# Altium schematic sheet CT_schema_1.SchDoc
size 461 x 273 mm
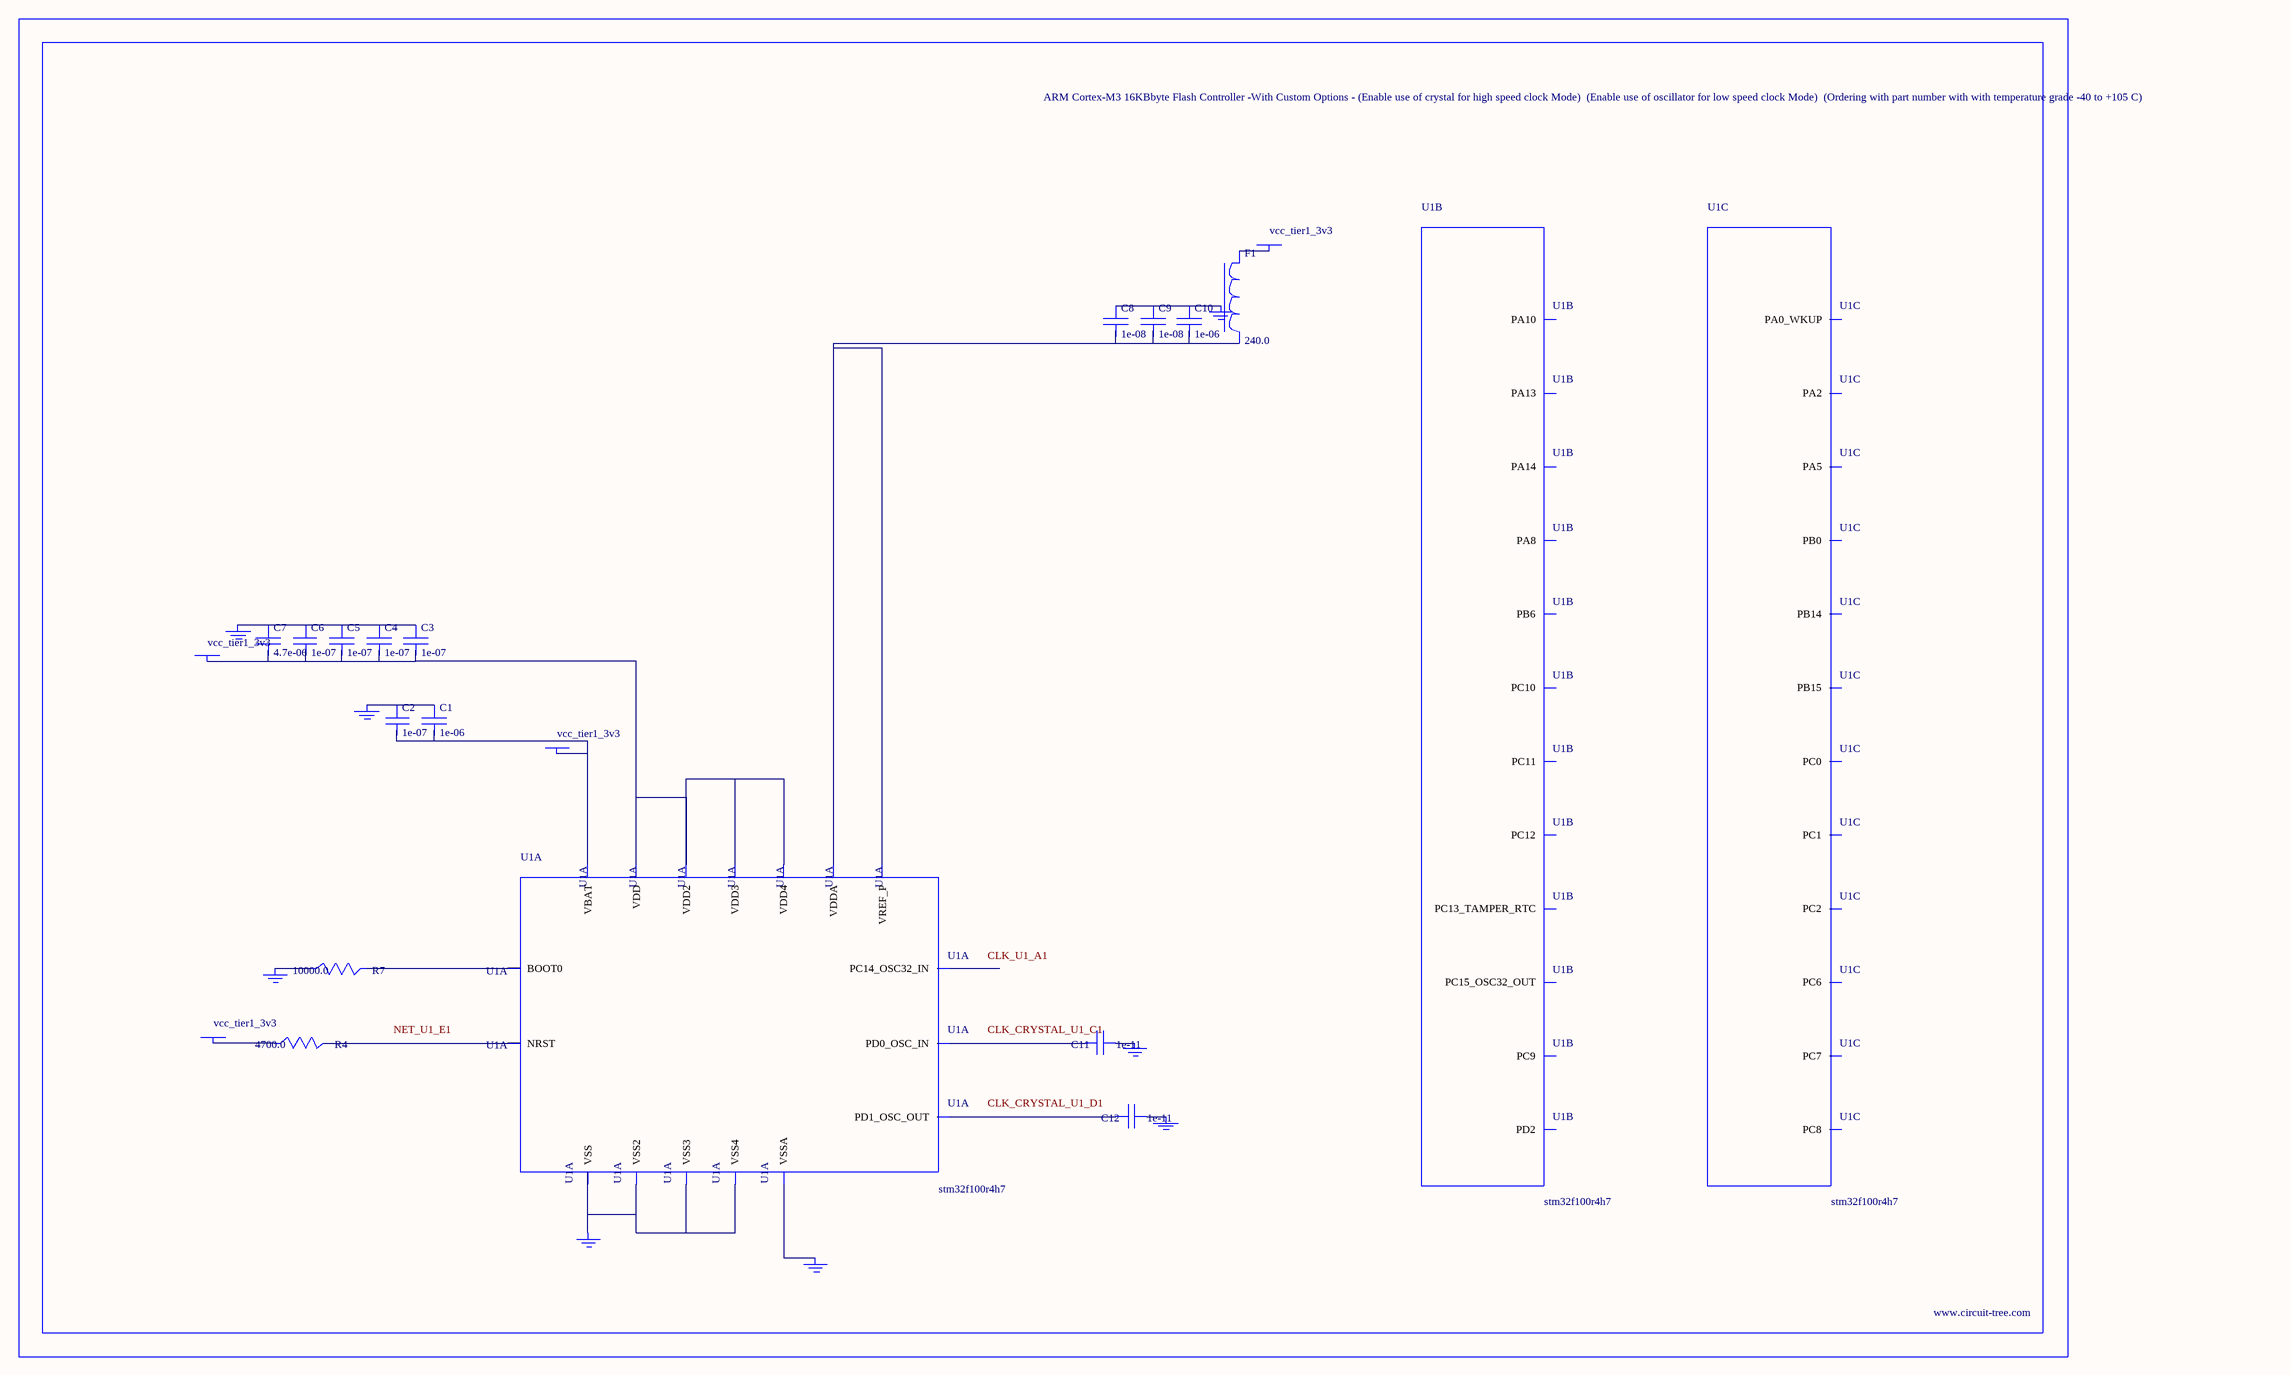
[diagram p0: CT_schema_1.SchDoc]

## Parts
BORDER0  (no value)
C1  1e-06  [C0603]
C2  1e-07  [C0603]
C3  1e-07  [C0603]
C4  1e-07  [C0603]
C5  1e-07  [C0603]
C6  1e-07  [C0603]
C7  4.7e-06  [C0603]
C8  1e-08  [C0603]
C9  1e-08  [C0603]
C10  1e-06  [C0603]
C11  1e-11  [C0402]
C12  1e-11  [C0402]
F1  240.0  [L0603]
GND_INSTANCE_0_0  (no value)
GND_INSTANCE_0_1  (no value)
GND_INSTANCE_0_2  (no value)
GND_INSTANCE_0_3  (no value)
GND_INSTANCE_0_4  (no value)
GND_INSTANCE_0_5  (no value)
GND_INSTANCE_0_6  (no value)
GND_INSTANCE_0_7  (no value)
POWER_INSTANCE_0_0  vcc_tier1_3v3
POWER_INSTANCE_0_1  vcc_tier1_3v3
POWER_INSTANCE_0_2  vcc_tier1_3v3
POWER_INSTANCE_0_3  vcc_tier1_3v3
R4  4700.0  [R0603]
R7  10000.0  [R0603]
U1  stm32f100r4h7  [TFBGA64]  (parts A,B,C of 5)

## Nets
NetC1_1: C1.1 C2.1 GND_INSTANCE_0_0.0(GND)
NetC1_2: C1.2 C2.2 POWER_INSTANCE_0_0.0(PWR) U1.B2(VBAT)
NetC3_1: C3.1 C4.1 C5.1 C6.1 C7.1 GND_INSTANCE_0_2.0(GND)
NetC3_2: C3.2 C4.2 C5.2 C6.2 C7.2 POWER_INSTANCE_0_2.0(PWR) U1.D2(VDD) U1.E4(VDD2) U1.E5(VDD3) U1.E6(VDD4)
NetC8_1: C8.1 C9.1 C10.1 GND_INSTANCE_0_1.0(GND)
NetC8_2: C8.2 C9.2 C10.2 F1.2 U1.G1(VREF_P) U1.H1(VDDA)
NetC11_1: C11.1 GND_INSTANCE_0_4.0(GND)
NetC11_2: C11.2 U1.C1(PD0_OSC_IN)
NetC12_1: C12.1 GND_INSTANCE_0_5.0(GND)
NetC12_2: C12.2 U1.D1(PD1_OSC_OUT)
NetF1_1: F1.1 POWER_INSTANCE_0_1.0(PWR)
NetGND_INSTANCE_0_3_0: GND_INSTANCE_0_3.0(GND) R7.1
NetGND_INSTANCE_0_6_0: GND_INSTANCE_0_6.0(GND) U1.F1(VSSA)
NetGND_INSTANCE_0_7_0: GND_INSTANCE_0_7.0(GND) U1.C2(VSS) U1.D4(VSS2) U1.D5(VSS3) U1.D6(VSS4)
NetPOWER_INSTANCE_0_3_0: POWER_INSTANCE_0_3.0(PWR) R4.1
NetR4_2: R4.2 U1.E1(NRST)
NetR7_2: R7.2 U1.B4(BOOT0)

Not connected (* = marked no-connect by the designer): U1 A1(PC14_OSC32_IN) A2(PC13_TAMPER_RTC) A7(PA14) A8(PA13) B1(PC15_OSC32_OUT) B5(PD2) B6(PC11) B7(PC10) C5(PC12) C6(PA10) D3(PB6) D7(PA8) D8(PC9) E2(PC1) E3(PC0) E7(PC7) E8(PC8) F2(PC2) F3(PA2) F4(PA5) F5(PB0) F6(PC6) F7(PB15) F8(PB14) G2(PA0_WKUP)

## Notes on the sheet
- Labels drawn without touching a wire or pin: CLK_CRYSTAL_U1_C1, CLK_CRYSTAL_U1_D1, CLK_U1_A1, NET_U1_E1

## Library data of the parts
BORDER0 = BORDER_PAGE0
C1 C10 = C0603C105K3RACTU
C2-C6 = 06035C104K4Z2A
C7 = GRM188R6YA475KE15D
C8 C9 = 06035C103K4Z2A
C11 C12 = C0402C100K3GACTU
F1 = Z0603C241ASMST
GND_INSTANCE_0_0-GND_INSTANCE_0_7 = GND
POWER_INSTANCE_0_0-POWER_INSTANCE_0_3 = PWR
R4 = RC0603JR-074K7L
R7 = RC0603JR-0710KL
